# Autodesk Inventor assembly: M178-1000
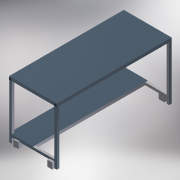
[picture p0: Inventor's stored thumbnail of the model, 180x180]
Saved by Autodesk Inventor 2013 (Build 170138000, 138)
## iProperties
Created: 2004-11
Part Number: M178-1000
Document SubType Name: Assembly
Designer: Autodesk, Inc.
Manufacturer: Standard
Standards Organization: Custom
Description: TABLE, MAIN
Mass: 47415.4 g
Surface Area: 115729 cm^2
Volume: 28165.2 cm^3
Density: 1.68348 g/cm^3
CAGE: 1LJX3
Dept. ID: Product Design
Description #2: ---
Finish #1: ---
Finish #2: ---
Material ID: ---
Project Number: ---
Author: Autodesk, Inc.
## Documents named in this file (15)
- Z:\_DATEN\Test Station\Components\M178-1000.iam
- Z:\_DATEN\Test Station\Components\M178-1001.ipt
- Z:\_DATEN\Test Station\Components\M178-1007.ipt
- Z:\_DATEN\Test Station\Components\M178-1005.ipt
- Z:\_DATEN\Test Station\Components\M178-1100.iam
- Z:\_DATEN\Test Station\Components\M178-1000-Phantom01.iam
- Z:\_DATEN\Test Station\Components\M178-1000_Leg_Phantom.iam
- Z:\_DATEN\Test Station\Components\18-813.ipt
- Z:\_DATEN\Test Station\Components\20-004.iam
- Z:\_DATEN\Test Station\Components\M178-100_Cross_Phantom.iam
- Z:\_DATEN\Test Station\Components\21-092 Caster Phantom.iam
- Z:\_DATEN\Test Station\Components\21-091 Caster Phantom.iam
- C:\Users\kelleyb.ADS\Desktop\Samples MIGRATED 2009 224 RTM_1\Standard Parts\Test Station Content\Extrusions\40 Series Profiles.ipt
- C:\Users\kelleyb.ADS\Desktop\Samples MIGRATED 2009 224 RTM_1\Standard Parts\Test Station Content\End Caps\18-xxx 40 Series End Caps.ipt
- Z:\_DATEN\Test Station\Components\M178-1000_Ersatzobjekt_1.ipt
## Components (44 placed, 12 different names)
1. M178-1001:1 — Mate:1, Flush:1, Flush:2, Insert:1
2. M178-1100:1 [sub-assembly] — Mate:1, Flush:1, Flush:2, Mate:2, Flush:3, Flush:4, Insert:8, Insert:9, Insert:10, Insert:11, Angle:5, Angle:6, Angle:7, Angle:8
3. M178-1005:1 — Mate:3, Flush:7, Insert:2, Angle:1, Insert:3, Angle:2, Mate:6, Flush:12, Flush:14, Mate:8, Flush:16, Mate:10, Flush:17, Flush:24
4. M178-1005:2 — Mate:5, Flush:11, Insert:4, Angle:3, Insert:5, Angle:4, Flush:19, Mate:12, Flush:20, Mate:14, Flush:21
5. 20-004:1 [sub-assembly] — Insert:2, Angle:1
6. 20-004:2 [sub-assembly] — Insert:3, Angle:2
7. 20-004:3 [sub-assembly] — Insert:5, Angle:4
8. 20-004:4 [sub-assembly] — Insert:4, Angle:3
9. M178-100_Cross_Phantom:1 [sub-assembly] — Mate:6, Flush:12, Flush:13, Flush:19, Flush:23
10. M178-100_Cross_Phantom:2 [sub-assembly] — Flush:14, Flush:15, Mate:7, Flush:22
11. 21-092 Caster Phantom:1 [sub-assembly] — Mate:10, Flush:17, Mate:11
12. 21-091 Caster Phantom:1 [sub-assembly] — Mate:8, Flush:16, Mate:9, Flush:18
13. 21-092 Caster Phantom:2 [sub-assembly] — Mate:14, Flush:21, Mate:15
14. 21-091 Caster Phantom:2 [sub-assembly] — Mate:12, Flush:20, Mate:13
15. M178-1007:1 — Flush:22, Flush:23, Flush:24, Insert:6, Insert:7
16. 18-813:1 — Insert:8, Angle:8
17. 18-813:2 — Insert:9, Angle:7
18. 18-813:3 — Insert:10, Angle:5
19. 18-813:4 — Insert:11, Angle:6
20. M178-1000_Ersatzobjekt_1:1
21. M178-1000-Phantom01:1 [sub-assembly] — Insert:1
22. M178-1000-Phantom01:11 [sub-assembly]
23. M178-1000-Phantom01:3 [sub-assembly]
24. M178-1000-Phantom01:4 [sub-assembly]
25. M178-1000-Phantom01:5 [sub-assembly]
26. M178-1000-Phantom01:6 [sub-assembly]
27. M178-1000-Phantom01:7 [sub-assembly]
28. M178-1000-Phantom01:8 [sub-assembly]
29. M178-1000-Phantom01:12 [sub-assembly]
30. M178-1000-Phantom01:10 [sub-assembly]
31. M178-1000_Leg_Phantom:1 [sub-assembly] — Mate:2, Flush:3, Flush:4, Mate:3, Flush:7, Flush:13, Mate:11, Mate:16
32. M178-1000_Leg_Phantom:2 [sub-assembly] — Flush:15, Mate:7, Mate:9
33. M178-1000_Leg_Phantom:3 [sub-assembly] — Mate:5, Flush:11, Mate:15
34. M178-1000_Leg_Phantom:4 [sub-assembly] — Mate:13
35. M178-1000-Phantom01:13 [sub-assembly] — Insert:6
36. M178-1000-Phantom01:15 [sub-assembly]
37. M178-1000-Phantom01:16 [sub-assembly]
38. M178-1000-Phantom01:17 [sub-assembly]
39. M178-1000-Phantom01:14 [sub-assembly] — Insert:7
40. M178-1000-Phantom01:18 [sub-assembly]
41. M178-1000-Phantom01:19 [sub-assembly]
42. M178-1000-Phantom01:20 [sub-assembly]
43. M178-1000-Phantom01:21 [sub-assembly]
44. M178-1000-Phantom01:22 [sub-assembly]
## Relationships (53: Flush 19, Mate 15, Insert 11, Angle 8)
- Mate:1: M178-1001:1 ↔ M178-1100:1
- Flush:1: M178-1001:1 ↔ M178-1100:1
- Flush:2: M178-1001:1 ↔ M178-1100:1
- Insert:1: M178-1001:1 ↔ M178-1000-Phantom01:1
- Mate:2: M178-1100:1 ↔ M178-1000_Leg_Phantom:1
- Flush:3: M178-1100:1 ↔ M178-1000_Leg_Phantom:1
- Flush:4: M178-1100:1 ↔ M178-1000_Leg_Phantom:1
- Mate:3: M178-1005:1 ↔ M178-1000_Leg_Phantom:1
- Flush:7: M178-1005:1 ↔ M178-1000_Leg_Phantom:1
- Mate:5: M178-1005:2 ↔ M178-1000_Leg_Phantom:3
- Flush:11: M178-1005:2 ↔ M178-1000_Leg_Phantom:3
- Insert:2: M178-1005:1 ↔ 20-004:1
- Angle:1: M178-1005:1 ↔ 20-004:1
- Insert:3: M178-1005:1 ↔ 20-004:2
- Angle:2: M178-1005:1 ↔ 20-004:2
- Insert:4: M178-1005:2 ↔ 20-004:4
- Angle:3: M178-1005:2 ↔ 20-004:4
- Insert:5: M178-1005:2 ↔ 20-004:3
- Angle:4: M178-1005:2 ↔ 20-004:3
- Mate:6: M178-1005:1 ↔ M178-100_Cross_Phantom:1
- Flush:12: M178-1005:1 ↔ M178-100_Cross_Phantom:1
- Flush:13: M178-100_Cross_Phantom:1 ↔ M178-1000_Leg_Phantom:1
- Flush:14: M178-1005:1 ↔ M178-100_Cross_Phantom:2
- Flush:15: M178-100_Cross_Phantom:2 ↔ M178-1000_Leg_Phantom:2
- Mate:7: M178-100_Cross_Phantom:2 ↔ M178-1000_Leg_Phantom:2
- Mate:8: M178-1005:1 ↔ 21-091 Caster Phantom:1
- Flush:16: M178-1005:1 ↔ 21-091 Caster Phantom:1
- Mate:9: 21-091 Caster Phantom:1 ↔ M178-1000_Leg_Phantom:2
- Mate:10: M178-1005:1 ↔ 21-092 Caster Phantom:1
- Flush:17: M178-1005:1 ↔ 21-092 Caster Phantom:1
- Mate:11: 21-092 Caster Phantom:1 ↔ M178-1000_Leg_Phantom:1
- Flush:18: 21-091 Caster Phantom:1
- Flush:19: M178-1005:2 ↔ M178-100_Cross_Phantom:1
- Mate:12: M178-1005:2 ↔ 21-091 Caster Phantom:2
- Flush:20: M178-1005:2 ↔ 21-091 Caster Phantom:2
- Mate:13: 21-091 Caster Phantom:2 ↔ M178-1000_Leg_Phantom:4
- Mate:14: M178-1005:2 ↔ 21-092 Caster Phantom:2
- Flush:21: M178-1005:2 ↔ 21-092 Caster Phantom:2
- Mate:15: 21-092 Caster Phantom:2 ↔ M178-1000_Leg_Phantom:3
- Flush:22: M178-100_Cross_Phantom:2 ↔ M178-1007:1
- Flush:23: M178-100_Cross_Phantom:1 ↔ M178-1007:1
- Flush:24: M178-1005:1 ↔ M178-1007:1
- Insert:6: M178-1007:1 ↔ M178-1000-Phantom01:13
- Insert:7: M178-1007:1 ↔ M178-1000-Phantom01:14
- Mate:16: M178-1000_Leg_Phantom:1
- Insert:8: M178-1100:1 ↔ 18-813:1
- Insert:9: M178-1100:1 ↔ 18-813:2
- Insert:10: M178-1100:1 ↔ 18-813:3
- Insert:11: M178-1100:1 ↔ 18-813:4
- Angle:5: M178-1100:1 ↔ 18-813:3
- Angle:6: M178-1100:1 ↔ 18-813:4
- Angle:7: M178-1100:1 ↔ 18-813:2
- Angle:8: M178-1100:1 ↔ 18-813:1
